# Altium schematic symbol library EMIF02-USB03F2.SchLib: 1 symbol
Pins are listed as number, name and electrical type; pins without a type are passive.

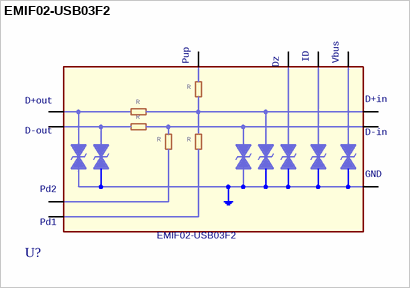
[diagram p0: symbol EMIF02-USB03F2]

## EMIF02-USB03F2
designator U?
footprint ST_CSP11N50P4X3_144X194X65
pins: A2 Dz, A3 ID, B1 Pd1, B2 Pup, B3 Vbus, C1 D+in, C2 Pd2, C3 D+out, D1 D-in, D2 GND, D3 D-out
